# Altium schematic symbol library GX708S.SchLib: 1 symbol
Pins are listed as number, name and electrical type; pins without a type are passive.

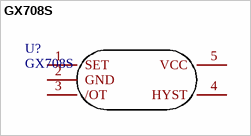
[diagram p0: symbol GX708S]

## GX708S
designator U?
footprint SOT-23-5
pins: 1 SET, 2 GND, 3 /OT, 4 HYST, 5 VCC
